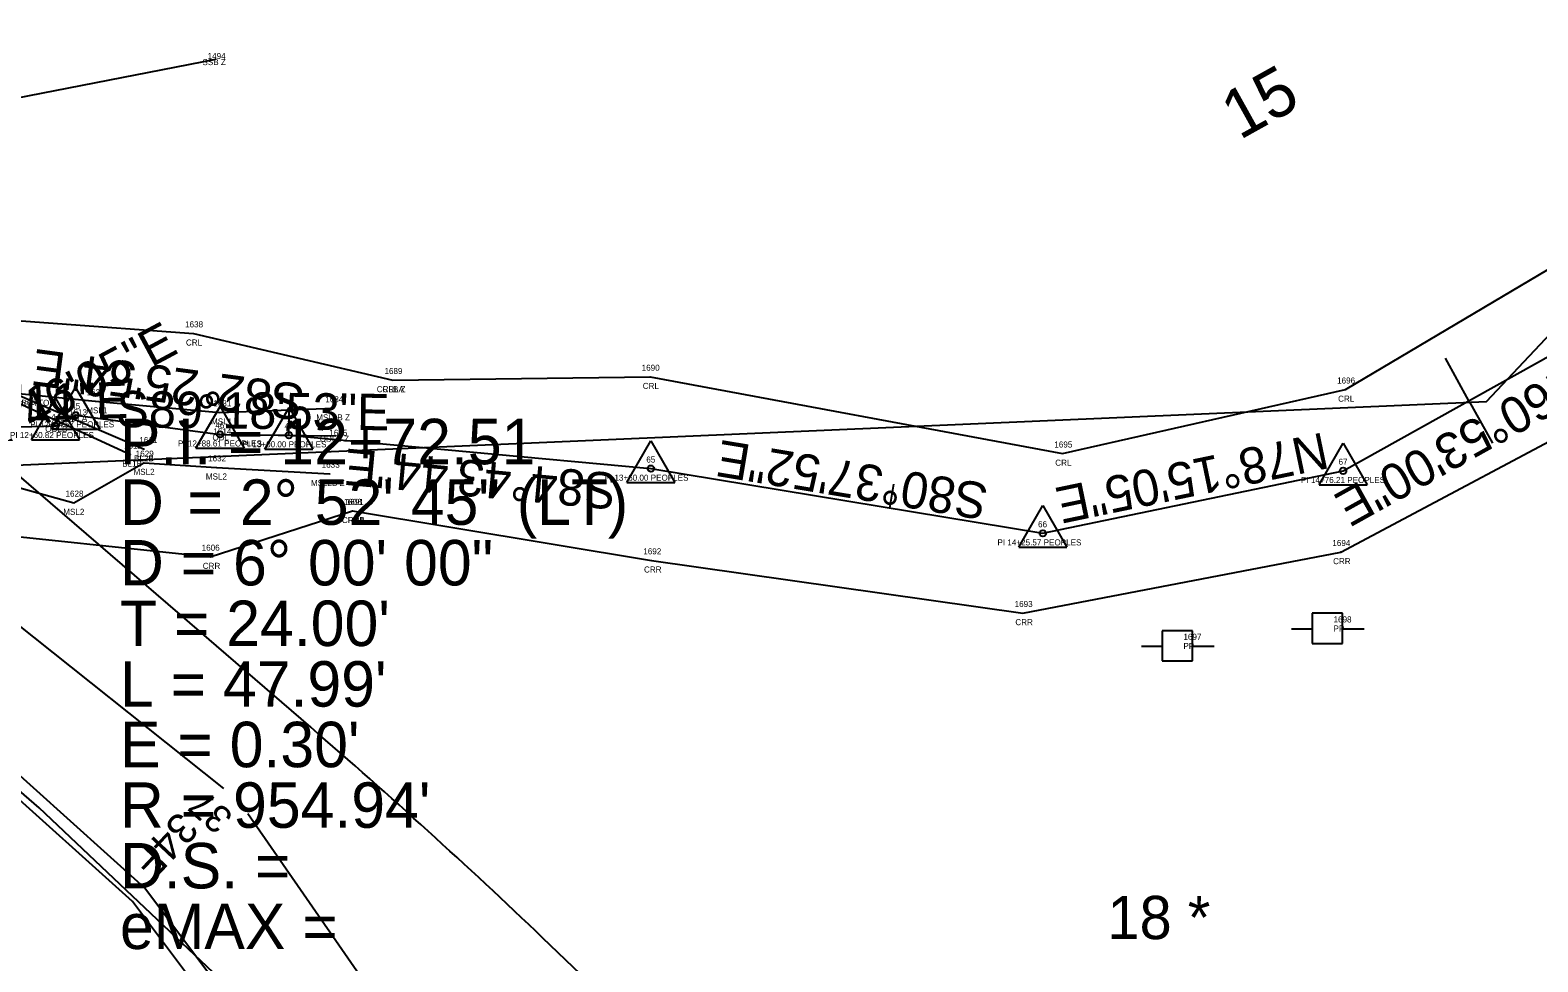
# Model space of a CAD drawing. Extents: x 1812113 to 1819860, y 1177395 to 1181185.
# Drawn here: x 1813853.2 to 1814102.1, y 1178641.9 to 1178795.6 of the extents above; entities that cross this region are included whole.
import ezdxf

# ---------------------------------------------------------------- set-up
doc = ezdxf.new("R2010")
doc.units = 0
for name, color, linetype in [('RD_DTM_BkLn1', 7, 'Continuous'), ('RD_EX_DV_Prop', 7, 'Continuous'), ('RD_EX_DV_TX_Prop', 7, 'Continuous'), ('RD_EX_H2O', 7, 'Continuous'), ('RD_EX_H2O_txCode', 7, 'Continuous'), ('RD_EX_Misc', 7, 'Continuous'), ('RD_EX_Misc_txCode', 7, 'Continuous'), ('RD_EX_UT', 7, 'Continuous'), ('RD_EX_UT_txCode', 7, 'Continuous'), ('RD_HC_CL', 7, 'Continuous'), ('RD_HC_Data', 7, 'Continuous'), ('RD_HC_Data_Tic', 7, 'Continuous'), ('RD_HC_TX_Sta50', 7, 'Continuous'), ('RD_HC_TX_StaOther', 7, 'Continuous'), ('RD_HC_txCode', 7, 'Continuous'), ('RD_PD_ALT1_TnTmp', 7, 'Continuous'), ('RD_PD_ALT3_LnLine', 7, 'Continuous'), ('RD_PD_BCA', 7, 'Continuous'), ('RD_PD_RW', 7, 'Continuous'), ('RD_SMD_Locator', 7, 'Continuous'), ('RD_SMD_Misc', 7, 'Continuous')]:
    doc.layers.add(name, color=color, linetype=linetype)

msp = doc.modelspace()

# ---------------------------------------------------------------- linework, layer by layer
at = {"layer": 'RD_DTM_BkLn1'}
for p, q in [((1813848.44, 1178735.38), (1813869.76, 1178725.59)), ((1813850.74, 1178735.64), (1813872.01, 1178726.49))]:
    msp.add_line(p, q, dxfattribs=at)
at = {"layer": 'RD_EX_DV_Prop'}
for p, q in [((1814093.61, 1178734.35), (1814151.15, 1178795.64)), ((1813850.78, 1178723.84), (1814093.61, 1178734.35)), ((1813854.67, 1178667.32), (1813781.84, 1178729.19)), ((1814011.17, 1178519.35), (1813854.67, 1178667.32))]:
    msp.add_line(p, q, dxfattribs=at)
at = {"layer": 'RD_EX_H2O'}
for points in [[(1813913.04, 1178737.89), (1813955.54, 1178738.43), (1814023.63, 1178725.76), (1814070.33, 1178736.32), (1814105.33, 1178757.05), (1814125.85, 1178779.62)], [(1813913.04, 1178737.89), (1813955.54, 1178738.43), (1814023.63, 1178725.76), (1814070.33, 1178736.32), (1814105.33, 1178757.05), (1814125.85, 1178779.62)], [(1813906.37, 1178716.29), (1813955.77, 1178708.13), (1814017.07, 1178699.44), (1814069.53, 1178709.51), (1814116.92, 1178734.67), (1814147.4, 1178772.34)], [(1813906.37, 1178716.29), (1813955.77, 1178708.13), (1814017.07, 1178699.44), (1814069.53, 1178709.51), (1814116.92, 1178734.67), (1814147.4, 1178772.34)], [(1813767.83, 1178739.34), (1813802.7, 1178746.65), (1813832.24, 1178749.11), (1813880.12, 1178745.59), (1813913.04, 1178737.89)], [(1813860.69, 1178732.09), (1813884.52, 1178728.93), (1813903.65, 1178728.7)], [(1813747.03, 1178677.41), (1813754.34, 1178684.8), (1813763.95, 1178688.13), (1813782.12, 1178708.31), (1813807.89, 1178720.63), (1813829.02, 1178714.89), (1813841.06, 1178713.13), (1813882.92, 1178708.73), (1813906.37, 1178716.29)]]:
    msp.add_lwpolyline(points, dxfattribs=at)
at = {"layer": 'RD_EX_Misc'}
for points in [[(1813573.26, 1178698.61), (1813581.18, 1178685.42), (1813588.27, 1178683.03), (1813621.87, 1178683.41), (1813652.09, 1178681.47), (1813685.62, 1178688.18), (1813723.85, 1178690.46), (1813735.91, 1178692.91), (1813768.22, 1178723.13), (1813784.54, 1178734.4), (1813800.79, 1178738.46), (1813839.24, 1178736.87), (1813863.9, 1178734.39), (1813884.49, 1178732.56), (1813903.28, 1178733.23)], [(1813591.15, 1178668.77), (1813628.98, 1178667.84), (1813655.76, 1178668.83), (1813686.95, 1178670.41), (1813726.51, 1178669.36), (1813738.94, 1178670.71), (1813788.68, 1178718.19), (1813806.25, 1178725.66), (1813819.18, 1178726.19), (1813847.08, 1178721.31), (1813860.38, 1178717.65), (1813871.97, 1178724.25), (1813883.92, 1178723.48), (1813902.67, 1178722.42)]]:
    msp.add_lwpolyline(points, dxfattribs=at)
at = {"layer": 'RD_EX_UT'}
for p, q in [((1814069.84, 1178699.4), (1814064.84, 1178699.4)), ((1814064.84, 1178699.4), (1814064.84, 1178694.4)), ((1814069.84, 1178699.4), (1814064.84, 1178699.4)), ((1814064.84, 1178699.4), (1814064.84, 1178694.4)), ((1814069.84, 1178694.4), (1814069.84, 1178699.4)), ((1814069.84, 1178694.4), (1814069.84, 1178699.4)), ((1814045.06, 1178696.53), (1814040.06, 1178696.53)), ((1814040.06, 1178696.53), (1814040.06, 1178691.53)), ((1814045.06, 1178696.53), (1814040.06, 1178696.53)), ((1814040.06, 1178696.53), (1814040.06, 1178691.53)), ((1814045.06, 1178691.53), (1814045.06, 1178696.53)), ((1814045.06, 1178691.53), (1814045.06, 1178696.53)), ((1814061.41, 1178696.84), (1814064.87, 1178696.84)), ((1814061.41, 1178696.84), (1814064.87, 1178696.84)), ((1814069.76, 1178696.84), (1814073.41, 1178696.84)), ((1814069.76, 1178696.84), (1814073.41, 1178696.84)), ((1814036.63, 1178693.97), (1814040.1, 1178693.97)), ((1814036.63, 1178693.97), (1814040.1, 1178693.97)), ((1814044.99, 1178693.97), (1814048.63, 1178693.97)), ((1814044.99, 1178693.97), (1814048.63, 1178693.97)), ((1814064.84, 1178694.4), (1814069.84, 1178694.4)), ((1814064.84, 1178694.4), (1814069.84, 1178694.4)), ((1814040.06, 1178691.53), (1814045.06, 1178691.53)), ((1814040.06, 1178691.53), (1814045.06, 1178691.53))]:
    msp.add_line(p, q, dxfattribs=at)
msp.add_lwpolyline([(1814122.48, 1178351.31), (1814099.73, 1178371.68), (1813807.05, 1178645.14), (1813817.45, 1178777.9), (1813883.81, 1178790.87)], dxfattribs=at)
at = {"layer": 'RD_HC_CL'}
for p, q in [((1814069.93, 1178722.91), (1814111.13, 1178745.86)), ((1813857.38, 1178730.32), (1813860.69, 1178732.09)), ((1813860.69, 1178732.09), (1813884.52, 1178728.93)), ((1813837.63, 1178729.78), (1813857.38, 1178730.32)), ((1813884.52, 1178728.93), (1813895.9, 1178728.79)), ((1813895.9, 1178728.79), (1813955.66, 1178723.28)), ((1813955.66, 1178723.28), (1814020.35, 1178712.6)), ((1814020.35, 1178712.6), (1814069.93, 1178722.91))]:
    msp.add_line(p, q, dxfattribs=at)
at = {"layer": 'RD_HC_Data'}
for p, q in [((1813856.72, 1178729.8), (1813860.69, 1178736.68)), ((1813860.69, 1178736.68), (1813864.66, 1178729.8)), ((1813853.41, 1178728.03), (1813857.38, 1178734.91)), ((1813857.38, 1178734.91), (1813861.35, 1178728.03)), ((1813880.55, 1178726.63), (1813884.52, 1178733.51)), ((1813884.52, 1178733.51), (1813888.49, 1178726.63)), ((1813891.93, 1178726.5), (1813895.91, 1178733.38)), ((1813895.91, 1178733.38), (1813899.87, 1178726.5)), ((1813856.72, 1178729.8), (1813864.66, 1178729.8)), ((1813853.41, 1178728.03), (1813861.35, 1178728.03)), ((1813880.55, 1178726.63), (1813888.49, 1178726.63)), ((1813891.93, 1178726.5), (1813899.87, 1178726.5)), ((1813951.69, 1178720.98), (1813955.66, 1178727.86)), ((1813955.66, 1178727.86), (1813959.63, 1178720.98)), ((1814065.96, 1178720.62), (1814069.93, 1178727.5)), ((1814069.93, 1178727.5), (1814073.9, 1178720.62)), ((1813951.69, 1178720.98), (1813959.63, 1178720.98)), ((1814065.96, 1178720.62), (1814073.9, 1178720.62)), ((1814016.38, 1178710.31), (1814020.35, 1178717.19)), ((1814020.35, 1178717.19), (1814024.32, 1178710.31)), ((1814016.38, 1178710.31), (1814024.32, 1178710.31))]:
    msp.add_line(p, q, dxfattribs=at)
for centre in [(1813860.69, 1178732.09), (1813857.38, 1178730.32), (1813884.52, 1178728.93), (1813895.9, 1178728.79), (1813955.66, 1178723.28), (1814069.93, 1178722.91), (1814020.35, 1178712.6)]:
    msp.add_circle(centre, 0.529, dxfattribs=at)
at = {"layer": 'RD_HC_Data_Tic'}
for p, q in [((1814090.71, 1178734.49), (1814086.82, 1178741.48)), ((1814090.71, 1178734.49), (1814094.6, 1178727.5)), ((1813895.9, 1178728.79), (1813895.95, 1178732.79)), ((1813995.12, 1178716.77), (1813995.77, 1178720.71))]:
    msp.add_line(p, q, dxfattribs=at)
at = {"layer": 'RD_PD_ALT3_LnLine'}
for p, q in [((1813872.03, 1178654.1), (1813834.82, 1178687.52)), ((1813870.07, 1178651.83), (1813832.86, 1178685.25)), ((1813903.58, 1178612.14), (1813872.03, 1178654.1)), ((1813901.51, 1178609.97), (1813870.07, 1178651.83))]:
    msp.add_line(p, q, dxfattribs=at)
at = {"layer": 'RD_PD_BCA'}
for p, q in [((1813885.13, 1178670.51), (1813845.96, 1178701.66)), ((1813919.31, 1178622.84), (1813889.1, 1178666.28))]:
    msp.add_line(p, q, dxfattribs=at)
at = {"layer": 'RD_PD_RW'}
for p, q in [((1813877.92, 1178699.21), (1813849.02, 1178724.14)), ((1813899.5, 1178680.59), (1813877.92, 1178699.21)), ((1813987.39, 1178598.51), (1813937.83, 1178645.81))]:
    msp.add_line(p, q, dxfattribs=at)
msp.add_arc((1813226.77, 1177900.71), 1029.94, 46.33932, 49.21843, dxfattribs=at)
at = {"layer": 'RD_SMD_Locator'}
for centre in [(1813883.81, 1178790.87), (1813880.12, 1178745.59), (1813913.04, 1178737.89), (1813913.04, 1178737.89), (1813913.04, 1178737.89), (1813955.54, 1178738.43), (1813955.54, 1178738.43), (1814070.33, 1178736.32), (1814070.33, 1178736.32), (1813863.9, 1178734.39), (1813860.69, 1178732.09), (1813860.69, 1178732.09), (1813884.49, 1178732.56), (1813903.28, 1178733.23), (1813857.38, 1178730.32), (1813857.38, 1178730.32), (1813884.52, 1178728.93), (1813884.52, 1178728.93), (1813895.9, 1178728.79), (1813872.01, 1178726.49), (1813903.65, 1178728.7), (1813869.76, 1178725.59), (1813871.97, 1178724.25), (1814023.63, 1178725.76), (1814023.63, 1178725.76), (1813883.92, 1178723.48), (1813902.67, 1178722.42), (1813955.66, 1178723.28), (1814069.93, 1178722.91), (1813860.38, 1178717.65), (1813906.37, 1178716.29), (1813906.37, 1178716.29), (1813906.37, 1178716.29), (1814020.35, 1178712.6), (1814069.53, 1178709.51), (1814069.53, 1178709.51), (1813882.92, 1178708.73), (1813955.77, 1178708.13), (1813955.77, 1178708.13), (1814017.07, 1178699.44), (1814017.07, 1178699.44)]:
    msp.add_circle(centre, 0.001, dxfattribs=at)

# ---------------------------------------------------------------- texts
at = {"layer": 'RD_EX_DV_TX_Prop'}
msp.add_text('18 *', height=7.14, dxfattribs=at).set_placement((1814031.02, 1178645.63))
at = {"layer": 'RD_EX_H2O_txCode'}
for s, p in [('1638', (1813878.75, 1178746.59)), ('CRL', (1813878.89, 1178743.59)), ('1639', (1813911.67, 1178738.89)), ('1689', (1813911.67, 1178738.89)), ('1689', (1813911.67, 1178738.89)), ('1690', (1813954.13, 1178739.43)), ('1690', (1813954.13, 1178739.43)), ('CRLB Z', (1813910.4, 1178735.89)), ('CRLA', (1813911.33, 1178735.89)), ('CRLA', (1813911.33, 1178735.89)), ('CRL', (1813954.31, 1178736.43)), ('CRL', (1813954.31, 1178736.43)), ('1696', (1814068.94, 1178737.32)), ('1696', (1814068.94, 1178737.32)), ('CRL', (1814069.11, 1178734.32)), ('CRL', (1814069.11, 1178734.32)), ('1607', (1813855.97, 1178730.32)), ('ODLA', (1813858.95, 1178731.09)), ('1613', (1813859.6, 1178732.09)), ('ODLB', (1813855.67, 1178729.32)), ('ODL', (1813883.27, 1178727.93)), ('1614', (1813883.43, 1178728.93)), ('1615', (1813902.57, 1178728.7)), ('ODLB Z', (1813900.99, 1178727.7)), ('1695', (1814022.26, 1178726.76)), ('1695', (1814022.26, 1178726.76)), ('CRL', (1814022.41, 1178723.76)), ('CRL', (1814022.41, 1178723.76)), ('1608', (1813904.96, 1178717.29)), ('1691', (1813905.29, 1178717.29)), ('1691', (1813905.29, 1178717.29)), ('CRRA', (1813904.63, 1178714.29)), ('CRRA', (1813904.63, 1178714.29)), ('CRRB', (1813904.65, 1178714.29)), ('1694', (1814068.16, 1178710.51)), ('1694', (1814068.16, 1178710.51)), ('1606', (1813881.49, 1178709.73)), ('1692', (1813954.4, 1178709.13)), ('1692', (1813954.4, 1178709.13)), ('CRR', (1813881.67, 1178706.73)), ('CRR', (1813954.52, 1178706.13)), ('CRR', (1813954.52, 1178706.13)), ('CRR', (1814068.28, 1178707.51)), ('CRR', (1814068.28, 1178707.51)), ('1693', (1814015.7, 1178700.44)), ('1693', (1814015.7, 1178700.44)), ('CRR', (1814015.82, 1178697.44)), ('CRR', (1814015.82, 1178697.44))]:
    msp.add_text(s, height=1, dxfattribs=at).set_placement(p)
at = {"layer": 'RD_EX_Misc_txCode'}
for s, p in [('1630', (1813862.49, 1178735.39)), ('1631', (1813883.41, 1178733.56)), ('1634', (1813901.9, 1178734.23)), ('MSL1', (1813862.44, 1178732.39)), ('MSL1', (1813883.04, 1178730.56)), ('MSL1B Z', (1813900.4, 1178731.23)), ('1629', (1813870.6, 1178725.25)), ('1632', (1813882.55, 1178724.48)), ('1633', (1813901.3, 1178723.42)), ('MSL2', (1813870.23, 1178722.25)), ('MSL2', (1813882.18, 1178721.48)), ('MSL2B Z', (1813899.52, 1178720.42)), ('1628', (1813859.01, 1178718.65)), ('MSL2', (1813858.64, 1178715.65))]:
    msp.add_text(s, height=1, dxfattribs=at).set_placement(p)
at = {"layer": 'RD_EX_UT_txCode'}
for s, p in [('1494', (1813882.47, 1178790.87)), ('SSB Z', (1813881.62, 1178789.87)), ('1698', (1814068.35, 1178697.89)), ('1698', (1814068.35, 1178697.89)), ('PP', (1814068.35, 1178696.39)), ('PP', (1814068.35, 1178696.39)), ('1697', (1814043.57, 1178695.02)), ('1697', (1814043.57, 1178695.02)), ('PP', (1814043.57, 1178693.52)), ('PP', (1814043.57, 1178693.52))]:
    msp.add_text(s, height=1, dxfattribs=at).set_placement(p)
at = {"layer": 'RD_HC_Data'}
for s, rotation, p in [('S82%%d25\'54"E', 172.4318, (1813898.65, 1178737.11)), ('N60%%d53\'00"E', 209.1167, (1814107.87, 1178740.9)), ('N78%%d15\'05"E', 191.7485, (1814066.69, 1178729.3)), ('S84%%d43\'44"E', 174.729, (1813950.26, 1178722.46)), ('S80%%d37\'52"E', 170.631, (1814011.6, 1178720.69))]:
    msp.add_text(s, height=6, rotation=rotation, dxfattribs=at).set_placement(p)
at = {"layer": 'RD_HC_TX_Sta50'}
msp.add_text('15', height=8, rotation=29.1167, dxfattribs=at).set_placement((1814052.85, 1178777.44))
at = {"layer": 'RD_HC_TX_StaOther'}
for s, p in [('P.I. = 12+72.51', (1813868, 1178724)), ('D', (1813868, 1178714)), ('    = 2%%d 52\' 45" (LT)', (1813868, 1178714)), ('D = 6%%d 00\' 00"', (1813868, 1178704)), ("T = 24.00'", (1813868, 1178694)), ("L = 47.99'", (1813868, 1178684)), ("E = 0.30'", (1813868, 1178674)), ("R = 954.94'", (1813868, 1178664)), ('D.S. = ', (1813868, 1178654)), ('eMAX = ', (1813868, 1178644))]:
    msp.add_text(s, height=7.5, dxfattribs=at).set_placement(p)
at = {"layer": 'RD_HC_txCode'}
for s, p in [('45', (1813859.95, 1178733.09)), ('44', (1813856.65, 1178731.32)), ('PI 12+60.82 PEOPLES', (1813849.84, 1178728.32)), ('PI 12+64.57 PEOPLES', (1813853.18, 1178730.09)), ('46', (1813883.76, 1178729.93)), ('47', (1813895.17, 1178729.79)), ('PI 12+88.61 PEOPLES', (1813877.58, 1178726.93)), ('PI 13+00.00 PEOPLES', (1813888.23, 1178726.79)), ('65', (1813954.9, 1178724.28)), ('67', (1814069.18, 1178723.91)), ('PI 13+60.00 PEOPLES', (1813948, 1178721.28)), ('PI 14+76.21 PEOPLES', (1814062.99, 1178720.91)), ('66', (1814019.57, 1178713.6)), ('PI 14+25.57 PEOPLES', (1814012.87, 1178710.6))]:
    msp.add_text(s, height=1, dxfattribs=at).set_placement(p)
at = {"layer": 'RD_PD_ALT1_TnTmp'}
for s, rotation, p in [('N61%%d46\'05"E', 28.2319, (1813837.79, 1178720.94)), ('N88%%d27\'11"E', 1.547, (1813823.92, 1178730.41)), ('S89%%d18\'53"E', 359.3146, (1813867.39, 1178730.13))]:
    msp.add_text(s, height=6, rotation=rotation, dxfattribs=at).set_placement(p)
at = {"layer": 'RD_PD_ALT3_LnLine'}
for s, height, rotation, p in [('37', 4.5, 138.8497, (1813886.93, 1178666.07)), ('34F', 5, 226.7234, (1813877.7, 1178666.95))]:
    msp.add_text(s, height=height, rotation=rotation, dxfattribs=at).set_placement(p)
at = {"layer": 'RD_SMD_Misc'}
for s, p in [('BL1A SHOALS TOP', (1813841.81, 1178733.38)), ('BL2A SHOALS BOTTOM', (1813842.3, 1178733.64)), ('1612', (1813868.68, 1178726.59)), ('1611', (1813871.21, 1178727.49)), ('BL1B', (1813868.37, 1178723.59)), ('BL2B', (1813870.33, 1178724.49))]:
    msp.add_text(s, height=1, dxfattribs=at).set_placement(p)

doc.saveas('drawing.dxf')
